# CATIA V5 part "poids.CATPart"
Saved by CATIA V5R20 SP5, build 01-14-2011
Part number: poids
Bounding box of the stored display mesh (mm): x -20 to 10, y 51.557 to 151.557, z -127.703 to 182.297
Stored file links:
  F:\projet\yyang_IAO\poids.CATPart
  F:\projet\yyang_IAO\iao.CATProduct
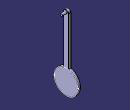
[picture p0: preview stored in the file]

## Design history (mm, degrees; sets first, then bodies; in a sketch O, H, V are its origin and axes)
External parameters (linked from other documents)
  External.epaisseur = 10 mm
  External.Largeur = 20 mm
  `External.rayon de liaison` = 5 mm
  `External.rayon du poids` = 50 mm
Set1
  Plane1: linked copy from another document
  Point1: linked copy from another document
  Point2: linked copy from another document
Set2
  Plane2: type Offset, RefPlane Plane1, Offset 10 {= External.epaisseur}, reversed
Body1 (main body)
  Sketch1 on Plane2, origin (-10, 0, 0), H (0, 1, 0), V (0, 0, 1)
    construction line L1 (101.5571, 172.2967) -> (101.5571, -77.7033)
    point P1 (101.5571, 172.2967)
    point P2 (101.5571, -77.7033)
    line L2 (111.5571, 172.2967) -> (111.5571, -77.7033)
    line L3 (91.5571, -77.7033) -> (91.5571, 172.2967)
    arc A1 centre (101.5571, -77.7033) radius 10 from (111.5571, -77.7033) to (91.5571, -77.7033) cw
    arc A2 centre (101.5571, 172.2967) radius 10 from (91.5571, 172.2967) to (111.5571, 172.2967) cw
    reference projected point E1 (101.5571, 172.2967) from Point1
    reference projected point E2 (101.5571, -77.7033) from Point2
    reference projected point E3 (101.5571, -77.7033) from Point2
    distance L1 L2 = 10 {= External.Largeur/2}
    tangency: A1 L2, A2 L2, A1 L3, A2 L3
    coincidence: P1 E1, P2 E2, P2 E3
  Pad1: profile Sketch1, direction (-1, 0, 0), length 10 {= External.epaisseur}
  Sketch2 on start face of Pad1, origin (-10, 0, 0), H (0, 1, 0), V (0, 0, 1)
    circle A1 centre (101.5571, 172.2967) radius 5
    point P1 (101.5571, 172.2967)
    reference projected point E1 (101.5571, 172.2967) from Point1
    reference projected point E2 (101.5571, 172.2967) from Point1
    distance A1 E2 = 5 {= `External.rayon de liaison`}
    coincidence: P1 E1
  Pad2: profile Sketch2, direction (1, 0, 0), length 20 {= External.epaisseur*2}
  Sketch3 on Plane2, origin (-10, 0, 0), H (0, 1, 0), V (0, 0, 1)
    circle A1 centre (101.5571, -77.7033) radius 50
    point P1 (101.5571, -77.7033)
    reference projected point E1 (101.5571, -77.7033) from Point2
    reference projected point E2 (101.5571, -77.7033) from Point2
    distance A1 E2 = 50 {= `External.rayon du poids`}
    coincidence: P1 E1
  Pad3: profile Sketch3, direction (-1, 0, 0), length 10 {= External.epaisseur}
